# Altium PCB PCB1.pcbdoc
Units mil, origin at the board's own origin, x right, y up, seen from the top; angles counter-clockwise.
Board outline 3045 x 3700 mil, 2 copper layers (Top Layer, Bottom Layer), stack 62.206 mil thick; 58 components, 52 nets, 178 pads, 29 vias.
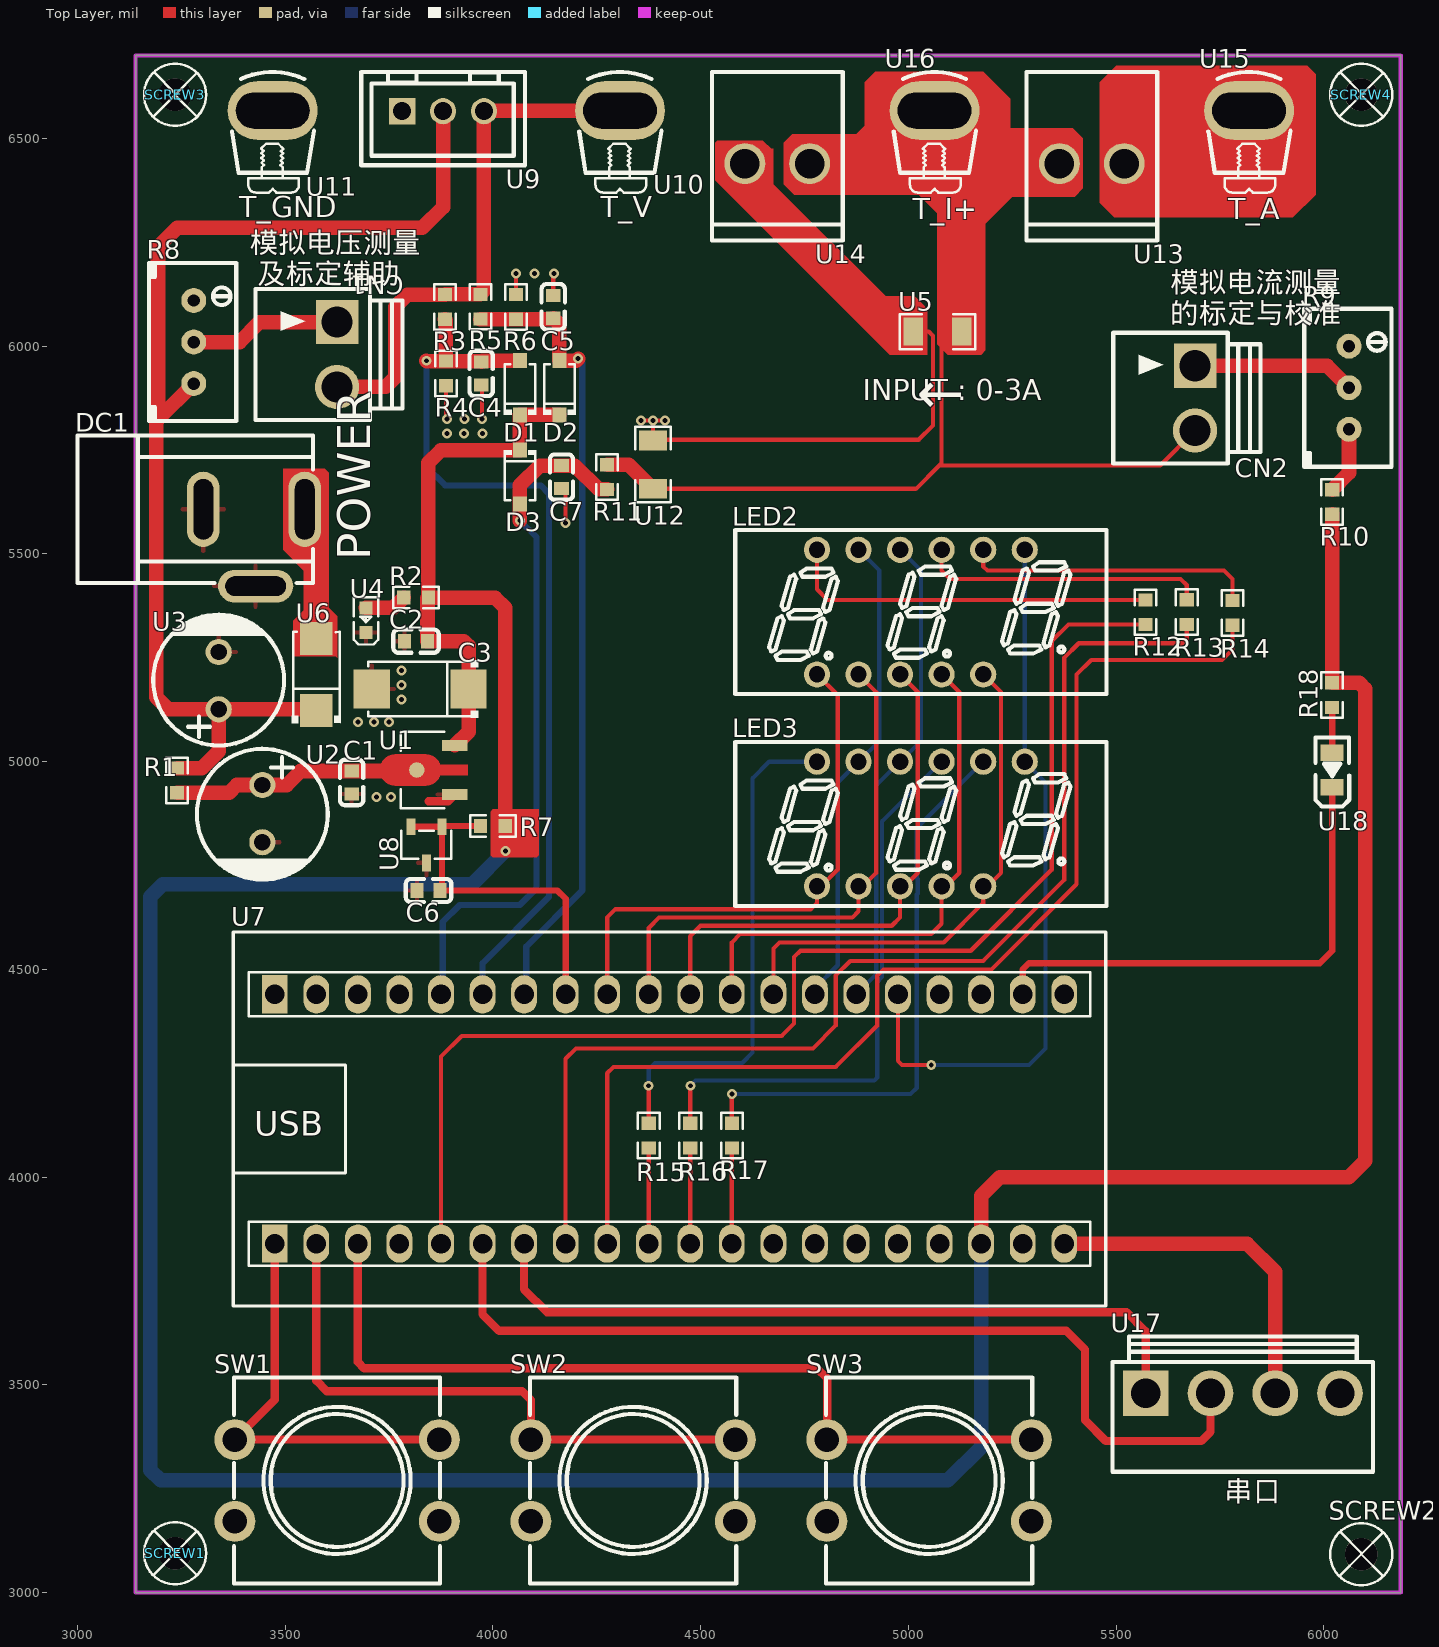
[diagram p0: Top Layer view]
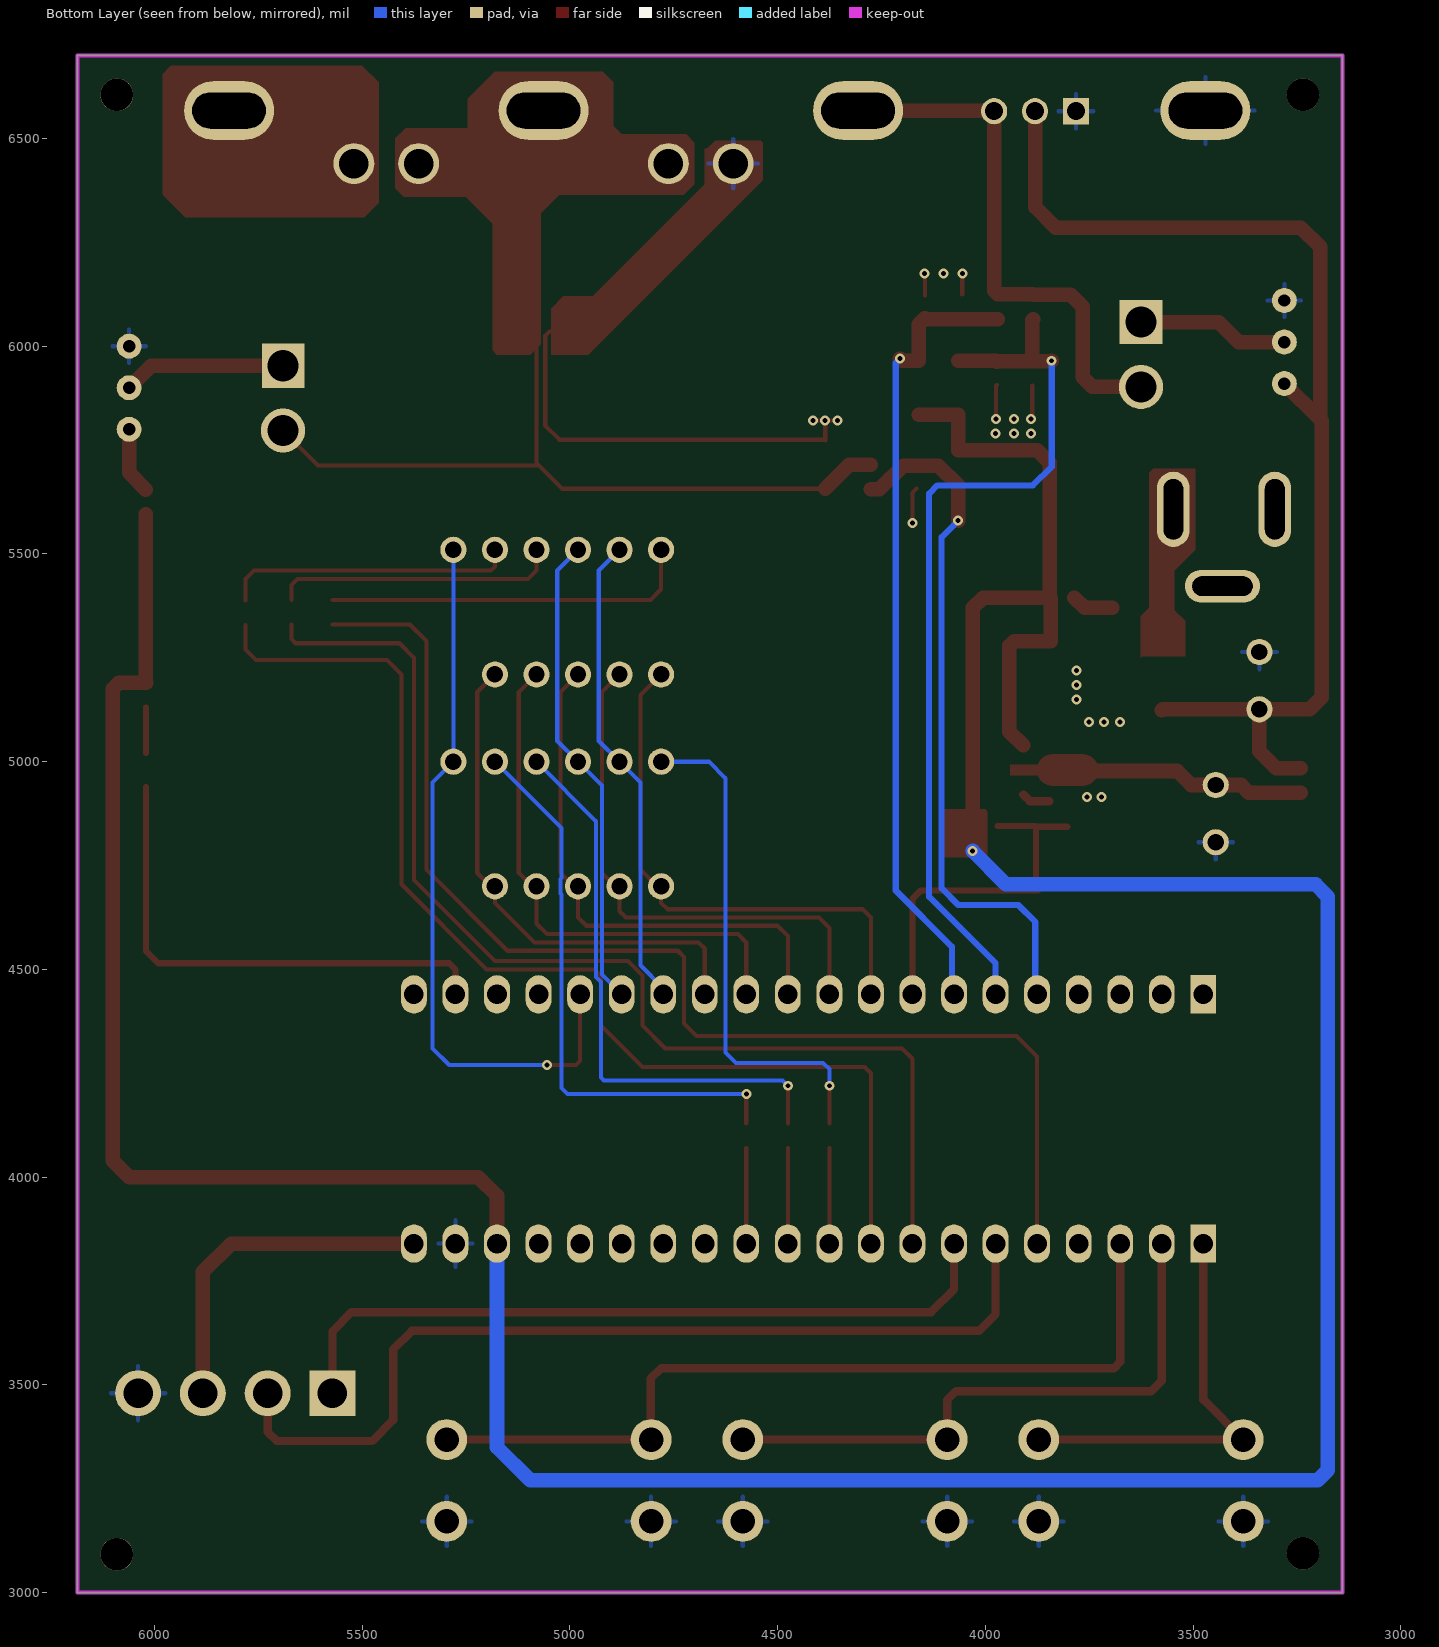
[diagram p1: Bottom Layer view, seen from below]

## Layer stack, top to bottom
Top Solder Mask Layer: solder mask 0.394, Dk 3.3
Top Layer: signal copper 1.379
Dielectric1: surface 59.449, FR4, Dk 4.5
Bottom Layer: signal copper 1.378
Bottom Solder Mask Layer: solder mask 0.394, Dk 3.3

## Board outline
3140.19,6700 3140.19,3000 6185.19,3000 6185.19,6700

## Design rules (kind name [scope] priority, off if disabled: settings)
BoardOutlineClearance copperThickness2oz_1 [All] p2 off: genericclearance=7.99 ignorepadtopadclearanceinfootprint=FALSE except(0: Arc-SplitContinuation Track-SplitContinuation SMDPad-SplitContinuation THPad-SplitContinuation Via-SplitContinuation Fill-SplitContinuation Region-SplitContinuation Poly-SplitContinuation Text-SplitContinuation Hole-SplitContinuation; 5.98: Arc-CutoutEdge SMDPad-CutoutEdge THPad-CutoutEdge Via-CutoutEdge Fill-CutoutEdge Region-CutoutEdge Text-CutoutEdge; 6.93: Hole-OutlineEdge Hole-CutoutEdge; 10: Poly-OutlineEdge Poly-CutoutEdge; 11.81: Arc-OutlineEdge Track-OutlineEdge SMDPad-OutlineEdge THPad-OutlineEdge Via-OutlineEdge Fill-OutlineEdge Region-OutlineEdge Text-OutlineEdge Track-CutoutEdge)
BoardOutlineClearance copperThickness1oz_1 [All] p4: genericclearance=4.02 ignorepadtopadclearanceinfootprint=FALSE except(0: Arc-SplitContinuation Track-SplitContinuation SMDPad-SplitContinuation THPad-SplitContinuation Via-SplitContinuation Fill-SplitContinuation Region-SplitContinuation Poly-SplitContinuation Text-SplitContinuation Hole-SplitContinuation; 6: SMDPad-CutoutEdge THPad-CutoutEdge Via-CutoutEdge Fill-CutoutEdge Region-CutoutEdge Text-CutoutEdge; 6.93: Hole-OutlineEdge Hole-CutoutEdge; 10: Poly-OutlineEdge Poly-CutoutEdge; 11.8: Arc-OutlineEdge Track-OutlineEdge SMDPad-OutlineEdge THPad-OutlineEdge Via-OutlineEdge Fill-OutlineEdge Region-OutlineEdge Text-OutlineEdge; 11.81: Arc-CutoutEdge Track-CutoutEdge)
Clearance copperThickness2oz [All] p1 off: gap=7.99 ignorepadtopadclearanceinfootprint=FALSE except(5.98: SMDPad-Track SMDPad-SMDPad THPad-Track SMDPad-THPad THPad-THPad Track-Via SMDPad-Via THPad-Via Via-Via Fill-Track Region-Track Fill-SMDPad Region-SMDPad Fill-THPad Region-THPad Fill-Via Region-Via Fill-Fill Fill-Region Region-Region Arc-Track Arc-SMDPad Arc-THPad Arc-Via Fill-Arc Region-Arc Arc-Arc Text-Track SMDPad-Text Text-THPad Text-Via Fill-Text Region-Text Arc-Text Text-Text; 6.93: Hole-Track Hole-SMDPad Hole-THPad Hole-Via Fill-Hole Region-Hole Hole-Arc Hole-Text; 10: Poly-Track Poly-SMDPad Poly-THPad Poly-Via Poly-Fill Poly-Region Poly-Poly Poly-Arc Poly-Text Poly-Hole)
Clearance copperThickness1oz [All] p3: gap=4.02 ignorepadtopadclearanceinfootprint=FALSE except(5.98: SMDPad-Track SMDPad-SMDPad THPad-Track SMDPad-THPad THPad-THPad Track-Via SMDPad-Via THPad-Via Via-Via Fill-Track Region-Track Fill-SMDPad Region-SMDPad Fill-THPad Region-THPad Fill-Via Region-Via Fill-Fill Fill-Region Region-Region; 6: Arc-Track Arc-SMDPad Arc-THPad Arc-Via Fill-Arc Region-Arc Arc-Arc Text-Track SMDPad-Text Text-THPad Text-Via Fill-Text Region-Text Arc-Text Text-Text; 6.93: Hole-Track Hole-SMDPad Hole-THPad Hole-Via Fill-Hole Region-Hole Hole-Arc Hole-Text; 10: Poly-Track Poly-SMDPad Poly-THPad Poly-Via Poly-Fill Poly-Region Poly-Poly Poly-Arc Poly-Text Poly-Hole)
Creepage creepage [All] p1: checkdistance=0 ignoreinternallayers=TRUE applytopolygonpour=TRUE
DiffPairsRouting differentialPair [All] p1: maxlimit=6 minlimit=6 mostfreqgap=6 toplayer_minwidth=5 toplayer_prefwidth=10 toplayer_maxwidth=100 toplayer_mingap=6 toplayer_prefgap=6 toplayer_maxgap=6 bottomlayer_minwidth=5 bottomlayer_prefwidth=10 bottomlayer_maxwidth=100 bottomlayer_mingap=6 bottomlayer_prefgap=6 bottomlayer_maxgap=6 maxuncoupledlength=10
HoleToHoleClearance otherClearance [All] p1: gap=11.81 allowstackedmicrovias=TRUE
Length netLength [All] p1: minlimit=0 maxlimit=0
MatchedLengths netLengthTolerance [All] p1: tolerance=1000
PasteMaskExpansion pasteMaskExpansion [All] p1: expansion=0
PlaneConnect innerPlane [All] p1: planeconnectstyle=Relief reliefexpansion=20 reliefentries=4 reliefconductorwidth=10 reliefairgap=10
PolygonConnect copperRegion [(InNet('$1N3') OR InNet('GND'))] p1: connectstyle=Relief reliefconductorwidth=10 reliefentries=4 polygonreliefangle="90 Angle" airgapwidth=10 via.connectstyle=Relief via.reliefconductorwidth=10 via.reliefentries=4 via.polygonreliefangle="90 Angle" via.airgapwidth=10
RoutingVias viaSize [All] p1: holewidth=12.01 width=24.02 viastyle="Through Hole" minholewidth=11.81 minwidth=19.68 maxholewidth=248.03 maxwidth=393.7
SolderMaskExpansion solderMaskExpansion [IsVia] p1: expansion=-1000 istentingtop=TRUE
SolderMaskExpansion solderMaskExpansion [All] p2: expansion=2 istentingtop=FALSE
Width copperThickness2oz_2 [All] p1 off: maxlimit=100 minlimit=8 preferedwidth=10
Width copperThickness1oz_2 [All] p2: maxlimit=100 minlimit=5 preferedwidth=10

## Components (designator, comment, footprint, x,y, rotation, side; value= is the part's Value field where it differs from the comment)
C1 "0.1uF" C0603 3660.19,4950 r90 top
C2 "100nF" C0603 3815.19,5290 r0 top
C3 "100uF 16V" CAP-SMD_L6.0-W3.2-FD 3825.19,5175 r180 top
C4 "10nF" C0603 3971.88,5934.49 r90 top
C5 "10nF" C0603 4145.31,6094.88 r270 top
C6 "100nF" C0603 3845.19,4690 r0 top
C7 "10nF" C0603 4165.19,5685 r90 top
CN1 "JP2D" CONN-TH_2P-P3.96-V 3625.19,5980 r270 top
CN2 "JP2D" CONN-TH_2P-P3.96-V 5690.19,5875 r270 top
D1 "1N4148" SOD-123_L2.7-W1.7-LS3.8-RD 4065.19,5900 r90 top
D2 "1N4148" SOD-123_L2.7-W1.7-LS3.8-RD 4160.19,5900 r90 top
D3 "1N4148" SOD-123_L2.7-W1.7-LS3.8-RD 4065.19,5685 r270 top
DC1 "DC005" DC-IN-TH_DC005 3425.19,5515 r0 top
LED2 "FJ2381AH" LED-SEG-TH_FJ2381AH 5030.19,5360 r0 top
LED3 "FJ2381AH" LED-SEG-TH_FJ2381AH 5030.19,4850 r0 top
R1 "10" R0603 3240.19,4955 r270 top
R2 "10K" R0603 3815.19,5395 r180 top
R3 "220K" R0603 3884.85,6094.66 r90 top
R4 "10K" R0603 3886.88,5934.37 r90 top
R5 "10K" R0603 3970.19,6095 r90 top
R6 "10K" R0603 4055.53,6094.66 r270 top
R7 "10K" R0603 4000.19,4845 r0 top
R8 "10K" RES-ADJ-TH_3296W 3280.19,6010 r0 top
R9 "10K" RES-ADJ-TH_3296W 6060.63,5900 r0 top
R10 "10K" R0603 6020.19,5625 r270 top
R11 "1K" R0603 4275.19,5685 r90 top
R12 "300" R0603 5570.53,5359.66 r90 top
R13 "300" R0603 5670.19,5360 r90 top
R14 "300" R0603 5780.42,5357.98 r90 top
R15 "300" R0603 4375.19,4100 r90 top
R16 "300" R0603 4475.19,4100 r90 top
R17 "300" R0603 4575.19,4100 r90 top
R18 "10K" R0603 6019.85,5160.34 r90 top
SCREW1 "" M2螺丝 3235.19,3094.77 r0 top
SCREW2 "" M2螺丝 6090.19,3092.32 r0 top
SCREW3 "" M2螺丝 3235.19,6605 r0 top
SCREW4 "" M2螺丝 6090.19,6605 r0 top
SW1 "B3F-4055" SW-TH_4P-L12.0-W12.0-P5.00-LS12.5 3625.19,3270 r0 top
SW2 "B3F-4055" SW-TH_4P-L12.0-W12.0-P5.00-LS12.5 4337.69,3270 r0 top
SW3 "B3F-4055" SW-TH_4P-L12.0-W12.0-P5.00-LS12.5 5050.19,3270 r0 top
U1 "SE8550K2-HF" SOT-89-3_L4.5-W2.5-P1.50-LS4.2-BR 3855.19,4980 r0 top
U2 "47uF/50V" CAP-TH_BD8.0-P3.50-D0.6-FD-2 3445.19,4875 r270 top
U3 "47uF/50V" CAP-TH_BD8.0-P3.50-D0.6-FD-2 3340.19,5195 r90 top
U4 "LED_0603" LED0603-RD_RED 3694.82,5340.65 r90 top
U5 "100mΩ" R1206 5070.19,6035 r0 top
U6 "1N5819" SMA_L4.3-W2.6-LS5.1-RD 3575.19,5210 r90 top
U7 "LCKFB-DWX-CW32F030C8T6" DIP-40_L53.34-W15.24-P2.54-LS15.24 4425.19,4140 r270 top
U8 "TL431ACDBZTG4" SOT-23-3_L3.0-W1.7-P0.95-LS2.9-BR 3840.19,4800 r90 top
U9 "XH-3A" CONN-TH_3P-P2.50_C9900023074 3880.19,6565.56 r180 top
U10 "T_V" TH-1_C9900016725 4306.02,6567.24 r0 top
U11 "T_GND" TH-1_C9900016725 3470.19,6567.24 r0 top
U12 "100m/1W" R1206 4385.19,5715 r90 top
U13 "CH3.96-2P直脚" CONN-TH_CH3.96-2P 5441.65,6439.6 r180 top
U14 "CH3.96-2P直脚" CONN-TH_CH3.96-2P 4684.57,6439.6 r180 top
U15 "T_V" TH-1_C9900016725 5820.19,6567.24 r0 top
U16 "T_V" TH-1_C9900016725 5063.11,6567.24 r0 top
U17 "HDR1X4_3.96mm" CONN-TH_4P-P3.96_FWF39601-S04S22W1B 5805.19,3480 r0 top
U18 "LEDGREEN0805" LED0805-R-RD_GREEN 6020.19,4980 r90 top

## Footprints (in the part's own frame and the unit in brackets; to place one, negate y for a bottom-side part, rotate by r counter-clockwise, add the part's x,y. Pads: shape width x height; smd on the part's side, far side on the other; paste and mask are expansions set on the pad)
C0603 [mm]
  rect 0.8x0.9 smd: 1(-0.7,0) 2(0.7,0)
  silkscreen extent -1.39,-0.71 1.39,0.71
CAP-SMD_L6.0-W3.2-FD [mil]
  rect 86.91x93.54 smd: 1(-116.58,0) 2(116.58,0)
  silkscreen extent -140,-69 125,69
CAP-TH_BD8.0-P3.50-D0.6-FD-2 [mm]
  round 1.6 hole 1: 1(-1.75,0) 2(1.75,0)
  silkscreen extent -3.96,-4 4.04,4
CONN-TH_2P-P3.96-V [mm]
  rect 2.7x2.6 hole 1.9: 1(-1.98,0)
  round 2.7 hole 1.9: 2(1.98,0)
  silkscreen extent -4,-5 4,4
CONN-TH_3P-P2.50_C9900023074 [mm]
  rect 1.6x1.6 hole 1.1: 1(2.5,0)
  round 1.6 hole 1.1: 2(0,0) 3(-2.5,0)
  silkscreen extent -5,-2.4 5,3.3
CONN-TH_4P-P3.96_FWF39601-S04S22W1B [mm]
  rect 2.8x2.8 hole 1.8: 1(-5.94,0)
  round 2.8 hole 1.8: 2(-1.98,0) 3(1.98,0) 4(5.94,0)
  silkscreen extent -7.96,-4.8 7.96,3.46
CONN-TH_CH3.96-2P [mm]
  round 2.5 hole 1.8 paste+0 mask+0.05: 1(-1.98,0) 2(1.98,0)
  silkscreen extent -4,-5.6 4,4.7
DC-IN-TH_DC005 [mm]
  oval 2x4.6 hole 1.2 slot 3.7 at 90 deg: 1(3.1,2.35) 2(-3.1,2.35)
  oval 4.6x2 hole 1.2 slot 3.7 at 0 deg: 3(0.1,-2.35)
  silkscreen extent -10.8,-2.15 3.6,6.85
DIP-40_L53.34-W15.24-P2.54-LS15.24 [mm]
  oval 2.337x1.575 hole 1.194: 1(-7.62,24.13) 2(-7.62,21.59) 3(-7.62,19.05) 4(-7.62,16.51) 5(-7.62,13.97) 6(-7.62,11.43) 7(-7.62,8.89) 8(-7.62,6.35) 9(-7.62,3.81) 10(-7.62,1.27) 11(-7.62,-1.27) 12(-7.62,-3.81) 13(-7.62,-6.35) 14(-7.62,-8.89) 15(-7.62,-11.43) 16(-7.62,-13.97) 17(-7.62,-16.51) 18(-7.62,-19.05) 19(-7.62,-21.59) 22(7.62,-21.59) 23(7.62,-19.05) 24(7.62,-16.51) 25(7.62,-13.97) 26(7.62,-11.43) 27(7.62,-8.89) 28(7.62,-6.35) 29(7.62,-3.81) 30(7.62,-1.27) 31(7.62,1.27) 32(7.62,3.81) 33(7.62,6.35) 34(7.62,8.89) 35(7.62,11.43) 36(7.62,13.97) 37(7.62,16.51) 38(7.62,19.05) 39(7.62,21.59) 40(7.62,24.13)
  rect 2.337x1.575 hole 1.194: 20(-7.62,-24.13) 21(7.62,-24.13)
  silkscreen extent -11.43,-26.67 11.43,26.67
LED0603-RD_RED [mm]
  rect 0.8x0.8 smd: 1(-0.749,-0.003) 2(0.749,0.003)
  silkscreen extent -1.49,-0.75 1.39,0.76
LED0805-R-RD_GREEN [mm]
  rect 1x1.4 smd: 1(1.05,0) 2(-1.05,0)
  silkscreen extent -2.22,-1.04 1.99,1.01
LED-SEG-TH_FJ2381AH [mm]
  round 1.6 hole 1: 1(-6.35,-3.81) 2(-3.81,-3.81) 3(-1.27,-3.81) 4(1.27,-3.81) 5(3.81,-3.81) 7(6.35,3.81) 8(3.81,3.81) 9(1.27,3.81) 10(-1.27,3.81) 11(-3.81,3.81) 12(-6.35,3.81)
  silkscreen extent -11.35,-5.01 11.35,5.01
M2螺丝 [mm]
  round 2 hole 2: 1(0,0)
  silkscreen extent -1.9,-1.9 1.9,1.9
R0603 [mil]
  rect 31.75x34.02 smd paste-3937.01 mask+2: 1(-29.66,0) 2(29.66,0)
  silkscreen extent -55,-26 55,26
R1206 [mil]
  rect 47.54x66.97 smd paste-3937.01 mask+2: 1(-58.22,0) 2(58.22,0)
  silkscreen extent -91,-42 91,42
RES-ADJ-TH_3296W [mil]
  round 60 hole 30: 1(0,100.01) 2(0,0.01) 3(0,-99.99)
  silkscreen extent -108,-190 102,190
SMA_L4.3-W2.6-LS5.1-RD [mm]
  rect 2x2 smd: 1(-2.2,0) 2(2.2,0)
  silkscreen extent -2.98,-1.5 2.6,1.5
SOD-123_L2.7-W1.7-LS3.8-RD [mm]
  rect 0.91x0.84 smd: 1(-1.655,0) 2(1.655,0)
  silkscreen extent -1.65,-1 1.43,1
SOT-23-3_L3.0-W1.7-P0.95-LS2.9-BR [mil]
  rect 40.85x20.95 smd: 1(43.36,-37.4) 2(43.36,37.4) 3(-43.36,0)
  silkscreen extent -34,-60 34,60
SOT-89-3_L4.5-W2.5-P1.50-LS4.2-BR [mm]
  rect 1.575x0.672 smd paste+0 mask+0.051: 1(1.356,-1.5) 3(1.356,1.5)
  round 0.95 smd: 2(-0.966,0)
  Top Layer region: -2.283,0.95 -0.429,0.95 -0.384,0.949 -0.34,0.946 -0.296,0.94 -0.252,0.933 -0.208,0.924 -0.165,0.912 -0.123,0.899 -0.081,0.884 -0.04,0.866 0,0.847 0.04,0.826 0.078,0.803 0.115,0.779 0.151,0.752 0.185,0.724 0.219,0.695 0.251,0.664 0.281,0.631 0.31,0.597 0.337,0.562 0.362,0.525 0.386,0.488 0.408,0.449 0.428,0.409 0.447,0.33 2.144,0.33 2.144,-0.33 0.447,-0.33 0.428,-0.409 0.408,-0.449 0.386,-0.488 0.362,-0.526 0.337,-0.562 0.31,-0.597 0.281,-0.631 0.251,-0.664 0.219,-0.695 0.185,-0.725 0.151,-0.753 0.115,-0.779 0.078,-0.804 0.04,-0.827 0,-0.848 -0.04,-0.867 -0.081,-0.884 -0.123,-0.899 -0.165,-0.913 -0.208,-0.924 -0.252,-0.934 -0.296,-0.941 -0.34,-0.946 -0.384,-0.949 -0.429,-0.95 -2.283,-0.95 -2.328,-0.949 -2.372,-0.946 -2.416,-0.941 -2.46,-0.934 -2.504,-0.924 -2.547,-0.913 -2.589,-0.899 -2.631,-0.884 -2.672,-0.867 -2.713,-0.848 -2.752,-0.827 -2.79,-0.804 -2.827,-0.779 -2.863,-0.753 -2.898,-0.725 -2.931,-0.695 -2.963,-0.664 -2.993,-0.631 -3.022,-0.597 -3.049,-0.562 -3.075,-0.526 -3.098,-0.488 -3.12,-0.449 -3.141,-0.409 -3.159,-0.369 -3.175,-0.327 -3.189,-0.285 -3.202,-0.242 -3.212,-0.199 -3.22,-0.155 -3.227,-0.111 -3.231,-0.067 -3.233,-0.022 -3.233,0.022 -3.231,0.067 -3.227,0.111 -3.22,0.155 -3.212,0.199 -3.202,0.242 -3.189,0.285 -3.175,0.327 -3.159,0.369 -3.141,0.409 -3.12,0.449 -3.098,0.488 -3.075,0.525 -3.049,0.562 -3.022,0.597 -2.993,0.631 -2.963,0.664 -2.931,0.695 -2.898,0.724 -2.863,0.752 -2.827,0.779 -2.79,0.803 -2.752,0.826 -2.713,0.847 -2.672,0.866 -2.631,0.884 -2.589,0.899 -2.547,0.912 -2.504,0.924 -2.46,0.933 -2.416,0.94 -2.372,0.946 -2.328,0.949
  silkscreen extent -1.95,-2.33 0.7,2.33
SW-TH_4P-L12.0-W12.0-P5.00-LS12.5 [mm]
  round 2.5 hole 1.5: 1(-6.25,2.5) 2(6.25,2.5) 3(-6.25,-2.5) 4(6.25,-2.5)
  silkscreen extent -6.3,-6.3 6.3,6.3
TH-1_C9900016725 [mm]
  oval 5.5x3.6 hole 2.2 slot 4.5 at 0 deg paste+0 mask+0.05: 1(0,0)
  silkscreen extent -2.49,-5.02 2.53,2.35

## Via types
v1: diameter 24.02, hole 12, Top Layer to Bottom Layer, 29 vias

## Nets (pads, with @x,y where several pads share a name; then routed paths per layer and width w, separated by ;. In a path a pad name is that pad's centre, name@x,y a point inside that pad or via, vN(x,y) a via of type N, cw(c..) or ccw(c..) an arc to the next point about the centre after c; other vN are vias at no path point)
3.3V: U7.40 U17.3 | length 828.1
  Top Layer w35: U7.40 5815.19,3840 5883.14,3772.05 U17.3
$1N3: DC1.1 U6.2
$1N5: C1.2 R1.2 U1.2 U2.1 | length 584.2
  Top Layer w35: R1.2 3365.53,4925.34 3384.09,4943.9 U2.1 3504.09,4943.9 3537.75,4977.56 C1.2 3799.36,4977.56 U1.2@3801.8,4979.99
$1N8: R2.2 U4.2 | length 101.2
  Top Layer w35: U4.2 3760.67,5370.14 R2.2
$1N91: CN1.1 R8.2 | length 364.9
  Top Layer w35: R8.2 3390.19,6010 3438.15,6057.95 CN1.1
$1N93: R9.3 R10.1 | length 162.1
  Top Layer w35: R10.1 6060.63,5695.1 R9.3
$1N95: CN2.1 R9.2 | length 392.4
  Top Layer w35: CN2.1 6007.68,5952.95 R9.2
$1N110: U13.1 U15.1
$1N128: LED2.12 R12.2 | length 896
  Top Layer w10: LED2.12 4780.19,5415 4805.87,5389.32 R12.2
$1N129: LED2.9 R13.2 | length 689.8
  Top Layer w10: LED2.9 5080.19,5460 5100.19,5440 5655.19,5440 5670.19,5425 R13.2
$1N130: LED2.8 R14.2 | length 704.9
  Top Layer w10: LED2.8 5180.19,5470 5190.19,5460 5760.19,5460 5780.19,5440 5780.19,5387.87 R14.2
$1N137: LED3.8 R17.2 | length 1374.9
  Top Layer w10: R17.2 v1(4575.19,4200)
  Bottom Layer w10: v1(4575.19,4200) 5005.19,4200 5020.19,4215 5020.19,4679.92 5022.67,4682.4 5022.67,4717.6 5020.19,4720.08 5020.19,4840 LED3.8
$1N138: LED3.9 R16.2 | length 1372.8
  Top Layer w10: R16.2 v1(4475.19,4220)
  Bottom Layer w10: v1(4475.19,4220) 4488.12,4232.93 4918.12,4232.93 4925.19,4240 4925.19,4470.18 4936.69,4481.67 4936.69,4856.5 LED3.9
$1N139: LED3.12 R15.2 | length 1228.5
  Top Layer w10: R15.2 v1(4375.19,4220)
  Bottom Layer w10: v1(4375.19,4220) 4375.19,4260 4390.19,4275 4600.19,4275 4625.19,4300 4625.19,4960 4665.19,5000 LED3.12
$1N147: R18.1 U18.1 | length 109.5
  Top Layer w15: R18.1 6020.19,5130.34 U18.1
+5V: C2.2 C3.1 D1.1 D2.1 D3.1 R2.1 R7.2 R10.2 R18.2 U1.3 U7.38 | length 9437
  Top Layer w35: U1.3 3941.77,5072.24 C3.1 3941.77,5278.42 3930.19,5290 C2.2 3842.75,5392.9 R2.1 ; R7.2 4030.19,4845.34 4030.19,5370 4005.19,5395 R2.1 ; D2.1 D1.1 D3.1 4065.03,5750 3875.19,5750 3844.85,5719.66 R2.1 ; U7.38 5175.19,3955 5220.19,4000 6060.19,4000 6100.19,4040 6100.19,5175 6085.19,5190 R18.2 6020.19,5190.34 R10.2
  Bottom Layer w35: v1(4030.19,4785) 3950.19,4705 3205.19,4705 3175.45,4675.25 3175.45,3294.75 3200.19,3270 5095.19,3270 5175.19,3350 U7.38
+V: CN1.2 R3.2 R5.2 U9.3 U10.1 | length 1309.3
  Top Layer w35: CN1.2 3742.24,5902.05 3765.19,5925 3765.19,6095 3794.51,6124.32 R3.2 3885.19,6124.66 R5.2 3978.61,6133.08 U9.3 3980.29,6567.24 U10.1
A: LED2.11 LED3.11 U7.7 | length 1154.9
  Bottom Layer w10: U7.7 4775.19,4455 4830.19,4510 4830.19,4950 LED3.11 4930.19,5050 4930.19,5460 LED2.11
ADC_IN8: C6.2 R7.1 U7.13 U8.1 U8.2 | length 864.5
  Top Layer w15: U8.2 U8.1 ; R7.1 3879.23,4845 U8.1 ; U7.13 4175.19,4670 4155.19,4690 C6.2 3877.59,4694.84 U8.1
ADC_IN9: C5.2 D2.2 R5.1 R6.2 U7.14 | length 1923.7
  Top Layer w35: R5.1 4055.19,6065.34 R6.2 4142.99,6065 C5.2 4160.19,6052.44 D2.2 4200.35,5965.16 v1(4205.19,5970)
  Bottom Layer w15: U7.14 4080.19,4445 4080.19,4555 4215.19,4690 4215.19,5960 v1(4205.19,5970)
ADC_IN11: C4.2 D1.2 R3.1 R4.2 U7.15 | length 2177.5
  Top Layer w35: v1(3840.19,5965) 3841.16,5964.03 R4.2 ; R3.1 3886.88,6062.98 R4.2 ; D1.2 3974.99,5965.16 C4.2 3969.9,5964.03 R4.2
  Bottom Layer w15: v1(3840.19,5965) 3840.19,5710 3885.19,5665 4115.19,5665 4135.19,5645 4135.19,4675 3975.19,4515 U7.15
ADC_IN12: C7.2 D3.2 R11.1 U7.16 | length 1675.2
  Top Layer w35: v1(4065.19,5580) D3.2 4065.19,5665 4112.75,5712.56 C7.2 4197.63,5712.56 4254.85,5655.34 R11.1
  Bottom Layer w15: U7.16 3879.59,4444.39 3879.59,4614.39 3920.19,4655 4065.19,4655 4105.19,4695 4105.19,5540 v1(4065.19,5580)
B: LED2.7 LED3.7 U7.5 | length 1756.4
  Top Layer w10: U7.5 4975.19,4280 4985.19,4270 v1(5055.19,4270)
  Bottom Layer w10: v1(5055.19,4270) 5290.19,4270 5330.19,4310 5330.19,4950 LED3.7 LED2.7
C: LED2.4 LED3.4 U7.9 | length 1289.7
  Top Layer w10: U7.9 4575.19,4565 4595.19,4585 5055.19,4585 5080.19,4610 LED3.4 5090.19,4700 5122.67,4732.48 5122.67,5167.52 LED2.4
COM1: R12.1 U7.25 | length 2992
  Top Layer w10: U7.25 3875.19,4290 3925.19,4340 4695.19,4340 4725.19,4370 4725.19,4530 4740.19,4545 5150.19,4545 5345.19,4740 5345.19,5290 5385.19,5330 R12.1
COM2: R13.1 U7.28 | length 2777.4
  Top Layer w10: U7.28 4175.19,4285 4200.19,4310 4770.19,4310 4825.19,4365 4825.19,4485 4860.19,4520 5180.19,4520 5375.19,4715 5375.19,5250 5410.19,5285 5660.19,5285 5670.19,5295 R13.1
COM3: R14.1 U7.29 | length 2762
  Top Layer w10: U7.29 4275.19,4250 4290.19,4265 4825.19,4265 4925.19,4365 4925.19,4485 4940.19,4500 5200.19,4500 5405.19,4705 5405.19,5210 5440.19,5245 5755.19,5245 5780.42,5270.23 R14.1
COM4: R15.1 U7.30 | length 230.3
  Top Layer w10: U7.30 R15.1
COM5: R16.1 U7.31 | length 230.3
  Top Layer w10: U7.31 R16.1
COM6: R17.1 U7.32 | length 230.3
  Top Layer w10: U7.32 R17.1
D: LED2.2 LED3.2 U7.11 | length 1292.6
  Top Layer w10: U7.11 4375.19,4600 4400.19,4625 4865.19,4625 4880.19,4640 LED3.2 4890.19,4700 4922.67,4732.48 4922.67,5167.52 LED2.2
DP: LED2.3 LED3.3 U7.10 | length 1289.7
  Top Layer w10: U7.10 4475.19,4580 4500.19,4605 4960.19,4605 4980.19,4625 LED3.3 4990.19,4700 5022.67,4732.48 5022.67,5167.52 LED2.3
E: LED2.1 LED3.1 U7.12 | length 1301.8
  Top Layer w10: U7.12 4275.19,4625 4295.19,4645 4765.19,4645 4780.19,4660 LED3.1 4790.19,4700 4830.19,4740 4830.19,5160 LED2.1
F: LED2.10 LED3.10 U7.6 | length 1154.9
  Bottom Layer w10: U7.6 4922.67,4487.48 4922.67,4942.48 LED3.10 5030.19,5050 5030.19,5460 LED2.10
G: LED2.5 LED3.5 U7.8 | length 1251.6
  Top Layer w10: U7.8 4675.19,4550 4690.19,4565 5085.19,4565 5180.19,4660 LED3.5 5190.19,4700 5222.67,4732.48 5222.67,5167.52 LED2.5
GND: C1.1 C2.1 C3.2 C4.1 C5.1 C6.1 C7.1 DC1.2 DC1.3 R4.1 R6.1 R8.1 R9.1 SW1.3 SW1.4 SW2.3 SW2.4 SW3.3 SW3.4 U1.1 U2.2 U3.2 U4.1 U5.1 U7.39 U8.3 U9.1 U11.1 U12.2 U14.2 U17.4 | length 1486.4
  Top Layer w10: R4.1 3886.88,5828.32 v1(3890.19,5825) ; C4.1 3973.8,5905.01 v1(3973.8,5825) ; v1(4055.19,6175) 4055.53,6174.66 R6.1 ; C5.1 4145.31,6173.56 v1(4146.75,6175) ; C7.1 4175.19,5647.44 v1(4175.19,5575) ; v1(4356.14,5821.1) v1(4385.19,5821.1) ; v1(4414.07,5821.1) v1(4385.19,5821.1) ; U5.1 5049.21,6035 5059.21,6025 5059.21,5809.02 5025.19,5775 4386.97,5775 U12.2 v1(4385.19,5821.1)
  Top Layer w20: 3845.19,4905 3892.64,4905 U1.1@3908.59,4920.94
  other v1: 3720.19,4915 3755.19,4915 3675.19,5095 3714.15,5095 3750.19,5095 3780.19,5150 3780.19,5185 3780.19,5220 3890.19,5790 3930.48,5790 3975.19,5790 3931.25,5825 4100.19,6175
I+: CN2.2 R11.2 U5.2 U12.1 U13.2 U14.1 U16.1 | length 1863.6
  Top Layer w10: U12.1 5018.04,5656.78 5074.48,5713.22 ; U5.2 5090.19,6035 5080.19,6025 5080.19,5718.94 5074.48,5713.22 ; CN2.2 5606.37,5713.22 5074.48,5713.22
  Top Layer w35: R11.2 4327.31,5714.66 U12.1
K1: SW1.1 SW1.2 U7.21 | length 1003.5
  Top Layer w20: U7.21 3475.19,3464.49 SW1.1 SW1.2
K2: SW2.1 SW2.2 U7.22 | length 1452.9
  Top Layer w20: U7.22 3575.19,3510 3600.19,3485 4070.19,3485 4091.63,3463.56 SW2.1 SW2.2
K3: SW3.1 SW3.2 U7.23 | length 2070.7
  Top Layer w20: U7.23 3675.19,3555 3690.19,3540 4780.19,3540 4805.19,3515 4805.19,3369.49 SW3.1 SW3.2
LED1: U7.2 U18.2 | length 1217.3
  Top Layer w15: U7.2 5275.19,4500 5290.19,4515 5990.19,4515 6020.19,4545 U18.2
MCU_RX: U7.27 U17.1 | length 1796.9
  Top Layer w20: U7.27 4075.19,3730 4130.19,3675 5525.19,3675 5571.33,3628.86 U17.1
MCU_TX: U7.26 U17.2 | length 2250.1
  Top Layer w20: U7.26 3975.19,3670 4015.19,3630 5380.19,3630 5425.19,3585 5425.19,3415 5475.19,3365 5705.19,3365 5727.24,3387.05 U17.2
PB5: U7.33
PB6: U7.34
PB7: U7.35
PB8: U7.36
PB9: U7.37
PB15: U7.24
PC14: U7.3
PC15: U7.4
VP: R1.1 R8.3 U3.1 U6.1 U9.2 | length 2779.7
  Top Layer w35: R1.1 3299.85,4984.66 3340.19,5025 U3.1 ; R8.3 3194.05,5823.85 ; U6.1 3572.48,5126.1 U3.1 ; U9.2 3880.18,6334.99 3830.19,6285 3240.19,6285 3194.05,6238.85 3194.05,5823.85 ; 3194.05,5823.85 3190.19,5820 3190.19,5155 3219.09,5126.1 U3.1
pads on no net: SCREW1.1 SCREW2.1 SCREW3.1 SCREW4.1 U7.1 U7.17 U7.18 U7.19 U7.20

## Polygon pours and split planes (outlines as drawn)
GND on Top Layer (solid, remove dead copper, pour order 0): 3525.19,5395 3465.19,5335 3465.19,5250 3435.19,5220 3315.19,5220 3290.8,5244.39 3290.8,5290.05 3280.19,5300.66 3280.19,5465 3230.19,5515 3230.19,5690 3255.19,5715 3340.19,5715 3380.19,5675 3380.19,5495 3480.19,5495 3525.19,5450
GND on Bottom Layer (solid, remove dead copper, pour order 12): 3455.19,4855 3485.19,4855 3500.19,4840 3500.19,4770 3473.3,4743.11 3222.08,4743.11 3175.19,4790 3175.19,5260 3225.19,5310 3380.19,5310 3385.19,5315 3400.19,5300 3400.19,5220 3373.24,5193.05 3258.24,5193.05 3235.19,5170 3235.19,4866.75 3246.97,4854.98 3455.22,4854.98
GND on Top Layer (solid, remove dead copper, pour order 2): 3611.9,4950 3698.41,4950 3698.41,4890.75 3564.55,4756.89 3418.3,4756.89 3400.19,4775 3400.19,4840 3415.19,4855 3516.9,4855
GND on Top Layer (solid, remove dead copper, pour order 4): 3945.19,4940 3945.19,4895 3941.62,4891.42 3816.73,4891.42 3795.24,4869.93 3632.24,4869.93 3632.24,4932.96 3630.19,4935 3635.19,4940
GND on Top Layer (solid, remove dead copper, pour order 6): 3655.19,5120 3655.19,5325 3660.19,5330 3800.19,5330 3805.19,5325 3805.19,5150 3775.19,5120
GND on Bottom Layer (solid, remove dead copper, pour order 14): 3767.28,5109.01 3767.28,5069.56 3755.19,5057.48 3755.19,4900 3705.19,4900 3705.19,5000 3660.19,5045 3660.19,5109.01
GND on Top Layer (solid, remove dead copper, pour order 8): 3795.19,5165 3795.19,5105 3765.19,5075 3660.19,5075 3660.19,5110 3664.1,5113.91 3750.19,5113.91 3765.19,5128.91 3765.19,5160 3770.19,5165
GND on Top Layer (solid, remove dead copper, pour order 10): 3770.19,4935 3781.43,4923.77 3781.43,4891.42 3765.19,4875.19 3765.19,4790 3770.19,4785 3855.19,4785 3855.19,4730 3840.19,4715 3840.19,4645 3835.19,4640 3760.19,4640 3705.19,4695 3705.19,4930 3710.19,4935
GND on Bottom Layer (solid, remove dead copper, pour order 16): 3165.19,6685 6135.19,6685 6155.19,6665 6155.19,3060.51 6143.09,3048.4 3216.8,3048.4 3210.19,3055 3210.19,3400 3290.19,3480 5385.19,3480 5810.19,3905 5810.19,5660 4505.19,5660 4405.19,5560 3765.19,5560 3560.19,5765 3560.19,5815 3190.19,5815 3185.19,5820 3185.19,6665
GND on Bottom Layer (solid, remove dead copper, pour order 18): 3820.19,5605 3800.19,5585 3800.19,5205 3765.19,5205 3740.19,5230 3740.19,5605
GND on Bottom Layer (solid, remove dead copper, pour order 20): 5395.19,3445 5335.19,3385 5235.19,3385 5220.19,3400 5220.19,3910 5225.19,3915 5310.19,3915 5395.19,3830

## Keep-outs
Board Outline Layer:
  the board outline again, w10

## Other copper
Top Layer:
  region net $1N3: 3595.19,5705 3605.19,5695 3605.19,5370 3625.19,5350 3625.19,5250 3621.65,5253.54 3519.05,5253.54 3519.05,5338.85 3545.19,5365 3545.19,5460 3495.19,5510 3495.19,5705
  region net $1N110: 5960.19,6675 5980.19,6655 5980.19,6365 5925.19,6310 5495.19,6310 5460.19,6345 5460.19,6635 5500.19,6675
  region net +5V: 4000.19,4886 4110.19,4886 4110.19,4775 4105.19,4770 4000.19,4770 3995.19,4775 3995.19,4880 4000.19,4885
  region net I+: 5095.19,5980 5070.19,6005 5070.19,6320 5025.19,6365 4725.19,6365 4700.19,6390 4700.19,6490 4720.19,6510 4875.19,6510 4895.19,6530 4895.19,6635 4920.19,6660 5180.19,6660 5245.19,6595 5245.19,6525 5395.19,6525 5420.19,6500 5420.19,6380 5400.19,6360 5250.19,6360 5185.19,6295 5185.19,5990 5175.19,5980
  region net GND: 4650.19,6495 4670.19,6475 4675.19,6475 4675.19,6390 4945.19,6120 5015.19,6120 5045.19,6090 5045.19,5980 4955.19,5980 4535.19,6400 4535.19,6490 4540.19,6495

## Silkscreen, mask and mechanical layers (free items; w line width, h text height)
Top Silkscreen Layer:
  text "T_GND" at 3390.19,6310 h50
  text "T_V" at 4260.19,6310 h50
  text "T_I+" at 5010.19,6305 h50
  text "T_A" at 5770.19,6305 h50
  text "模拟电压测量 /  及标定辅助" at 3415.19,6150 h50
  text "模拟电流测量 / 的标定与校准" at 5630.19,6055 h50
  text "INPUT : 0-3A" at 4890.19,5870 h50
  text "←" at 5020.19,5840 h100
  text "POWER" at 3705.19,5485 h80 r90
  text "串口" at 5760.19,3220 h50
